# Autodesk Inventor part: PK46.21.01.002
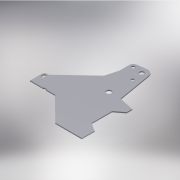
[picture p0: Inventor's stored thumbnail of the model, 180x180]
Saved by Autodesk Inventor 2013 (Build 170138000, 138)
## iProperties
Created: 2005-04
Part Number: PK46.21.01.002
Material: Steel, Mild
Document SubType Name: Modeling
Designer: salex
Manufacturer: Standard
Standards Organization: Custom
Density: 7.86 g/cm^3
Author: salex
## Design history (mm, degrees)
sketch "Эскиз1"
  geometry: L1 (-88.309, 65.586)-(-215.351, -105.47); L2 (108.403, 18.678)-(215, -600); L3 (215, -600)-(485, -660); L4 (485, -660)-(485, -760); L5 (485, -760)-(335, -875); L6 (335, -875)-(335, -1250); L7 (335, -1250)-(485, -1350); L8 (485, -1350)-(485, -1580); L9 (485, -1580)-(0, -1580); L10 (0, -1580)-(-441.092, -1146.749); L11 (-900, -1138)-(-900, -928); L12 (-850, -878)-(-820, -878); L13 (-820, -878)-(-300, -388); L14 (-300, -388)-(-235.759, -147.715); L15 (-734.851, -1950)-(865.233, -1950); L16 (-611.78, -1178)-(-880.629, -1178); L17 (49.507, -1600)-(334.18, -1600); L18 (-825, -928)-(-825, -958); L19 (-875, -928)-(-875, -958); L20 (-665, -1138)-(-655, -1123); L21 (-655, -1123)-(-615, -1123); L22 (-615, -1123)-(-605, -1138); L23 (-461.773, -1138)-(-605, -1138); L24 (-665, -1138)-(-900, -1138); L25 (-461.773, -1138)-(-458.773, -1135); L26 (-458.773, -1135)-(-448.773, -1135); L27 (-448.773, -1135)-(-441.092, -1142.544); L28 (-441.092, -1142.544)-(-441.092, -1146.749); L29 (-441.092, -1146.749)-(-450, -1138); L30 (-450, -1138)-(-461.773, -1138); C1 r 40 at (0, 0); C2 r 45 at (0, -600); C3 r 746 at (-750, -1273); A1 r 110 centre (0, 0) between (108.403, 18.678) and (-88.309, 65.586); A2 r 125 centre (-115, -180) between (-215.351, -105.47) and (-235.759, -147.715); A3 r 50 centre (-850, -928) between (-850, -878) and (-900, -928); A4 r 25 centre (-850, -928) between (-825, -928) and (-875, -928); A5 r 25 centre (-850, -958) between (-875, -958) and (-825, -958)
  constraints: 60 end point, 11 parallel, 10 point on circle, 10 tangent, 8 centre point, 4 perpendicular, 3 collinear, 2 coincident, 1 equal length, 1 equal radius, 1 horizontal, 1 other
  dimensions: "d0" = 600 distance of C2.centre C1.centre; "d1" = 80 diameter of C1; "d2" = 90 diameter of C2; "d3" = 0 horizontal distance of C2.centre C1.centre; "d4" = 230 distance of L7.end L8.end; "d5" = 110 radius of A1; "d6" = 125 radius of A2; "d7" = 115 horizontal distance of C1.centre A2.centre; "d8" = 300 horizontal distance of L13.end C2.centre; "d9" = 50 radius of A3; "d10" = 50 diameter of A4; "d12" = 900 distance from line of L11 C1.centre; "d13" = 485 distance from line of L4 C1.centre; "d16" = 330 distance from line of L6.end L9; "d17" = 100 distance of L3.end L4.end; "d21" = 980 distance from line of C2.centre L9; "d22" = 335 distance from line of L6 C2.centre; "d24" = 485 distance of L8.end L9.end; "d25" = 677 distance from line of L15 C3.centre; "d26" = 1492 diameter of C3; "d27" = 750 horizontal distance of C2.centre C3.centre; "d28" = 95 distance from line of L16 C3.centre; "d30" = 20 distance between parallel lines of L9 L17; "d31" = 350 distance between parallel lines of L15 L17 (derived); "d33" = 660 vertical distance of L3.end C1.centre; "d34" = 215 vertical distance of L5.end L3.end; "d36" = 180 vertical distance of A2.centre C1.centre; "d54" = 1950 distance from line of C1.centre L15 (derived); "d55" = 60 vertical distance of L2.end L3.end; "d58" = 30 distance of A4.centre A5.centre; "d59" = 0 horizontal distance of A5.centre A4.centre; "d65" = 40 distance of L20.end L21.end; "d66" = 235 distance from line of L20.start L11; "d69" = 442 distance between parallel lines of L9 L24; "d70" = 260 distance between parallel lines of L24 L12; "d71" = 750 distance from line of L13.end L24; "d73" = 15 vertical distance of L20.start L20.end; "d74" = 450 horizontal distance of C2.centre L29.end; "d75" = 3 distance between parallel lines of L26 L23; "d76" = 3 distance between parallel lines of L27 L29 (derived); "d77" = 45 deg angle of L30 L25; "d79" = 10 distance of L27.end L29.end (derived); "d81" = 10 distance of L25.end L26.end; "d95" = 10 horizontal distance of L20.start L20.end; "d96" = 215 horizontal distance of L2.end C1.centre; "d97" = 80 distance from line of L12.end L11
extrude "Выдавливание1" new body sketch "Эскиз1" distance "d37" = 20; taper "d38" = 0 deg
sketch "Эскиз2"
  geometry: L1 (16.283, 108.788)-(180.362, 84.229); L2 (240, 15)-(240, -202.517); L3 (240, -202.517)-(16.283, 108.788); C1 r 40 at (0, 0) reference; C2 r 30 at (170, 15); A1 r 110 centre (0, 0) between (88.309, 65.586) and (-108.403, 18.678) reference; A2 r 70 centre (170, 15) between (240, 15) and (180.362, 84.229)
  constraints: 6 end point, 3 point on circle, 3 tangent, 2 centre point, 1 coincident, 1 vertical
  dimensions: "d49" = 60 diameter of C2; "d50" = 170 horizontal distance of C2.centre C1.centre; "d51" = 15 vertical distance of C2.centre C1.centre; "d52" = 140 diameter of A2
extrude "Выдавливание2" join sketch "Эскиз2" stored distance "d43" = 10; taper "d44" = 0 deg
sketch "Эскиз5"
  geometry: C1 r 40 at (0, 0) reference; C2 r 26 at (25, -190)
  constraints: 1 centre point
  dimensions: "d62" = 52 diameter of C2; "d63" = 25 horizontal distance of C2.centre C1.centre; "d64" = 190 vertical distance of C2.centre C1.centre
extrude "Выдавливание4" cut sketch "Эскиз5" stored distance "d60" = 10; taper "d61" = 0 deg
fillet "Сопряжение2" dims "d80" = 10
body "Solid1"
other parameters: "d15" = 442, "d67" = 45 deg, "d68" = 45 deg
